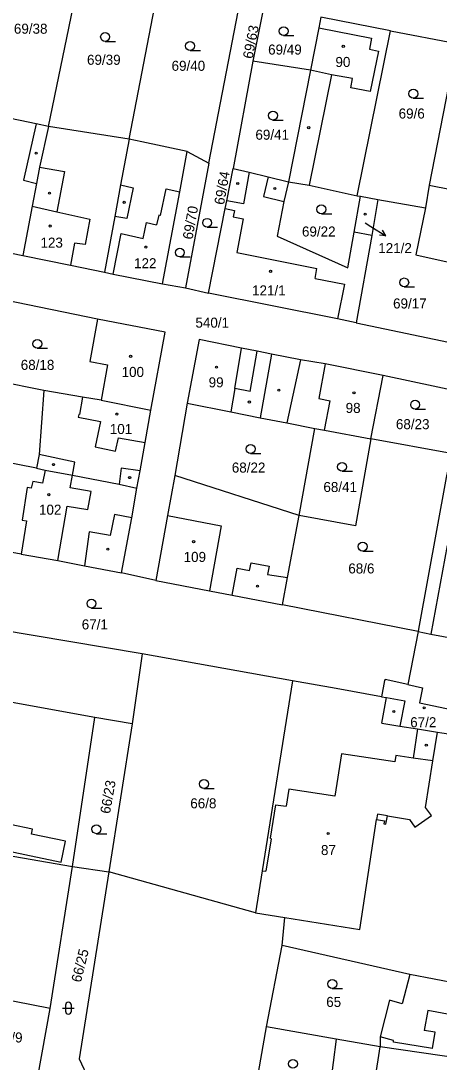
# Model space of a CAD drawing. Extents: x -758582 to -751794, y -998770 to -994350.
# Drawn here: x -756568.2 to -756497.4, y -996870.6 to -996694.2 of the extents above; entities that cross this region are included whole.
import ezdxf

# ---------------------------------------------------------------- set-up
doc = ezdxf.new("R2010")
doc.units = 0
for name, color, linetype in [('Hranice parcel', 7, 'Continuous'), ('Parcelní čísla', 7, 'Continuous'), ('Pop  PČ popisy', 7, 'Continuous'), ('Vnitřní kresba', 7, 'Continuous'), ('Značky budov', 7, 'Continuous'), ('Značky kultur', 7, 'Continuous')]:
    doc.layers.add(name, color=color, linetype=linetype)

msp = doc.modelspace()

# ---------------------------------------------------------------- linework, layer by layer
at = {"layer": 'Hranice parcel'}
for p, q in [((-756563.55, -996712.15), (-756558.07, -996685.62)), ((-756549.87, -996714.27), (-756544.86, -996688.3)), ((-756536.42, -996718.33), (-756531.1, -996690.92)), ((-756527.09, -996691.75), (-756528.96, -996701.04)), ((-756505.62, -996695.91), (-756517.41, -996693.6)), ((-756511.28, -996723.85), (-756505.62, -996695.91)), ((-756505.62, -996695.91), (-756494.42, -996698.08)), ((-756528.96, -996701.04), (-756532.3, -996719.25)), ((-756519.19, -996702.61), (-756528.96, -996701.04)), ((-756519.19, -996702.61), (-756522.92, -996721.49)), ((-756549.87, -996714.27), (-756563.55, -996712.15)), ((-756540.07, -996716.36), (-756536.42, -996718.33)), ((-756536.42, -996718.33), (-756540.33, -996739.42)), ((-756511.79, -996730), (-756510.7, -996723.94)), ((-756511.28, -996723.85), (-756510.7, -996723.94)), ((-756510.7, -996723.94), (-756507.76, -996724.5)), ((-756507.76, -996724.5), (-756508.8, -996730.61)), ((-756507.76, -996724.5), (-756499.71, -996725.9)), ((-756508.8, -996730.61), (-756511.79, -996730)), ((-756508.8, -996730.61), (-756511.47, -996745.39)), ((-756544.26, -996738.78), (-756540.33, -996739.42)), ((-756540.33, -996739.42), (-756536.47, -996740.33)), ((-756555.24, -996744.76), (-756570.89, -996741.53)), ((-756511.47, -996745.39), (-756491.64, -996749.52)), ((-756525.81, -996750.65), (-756527.73, -996761.44)), ((-756564.37, -996756.81), (-756573.85, -996754.94)), ((-756508.94, -996765), (-756506.9, -996754.31)), ((-756492.81, -996757.29), (-756506.9, -996754.31)), ((-756554.62, -996758.49), (-756546.23, -996760.16)), ((-756540.05, -996758.95), (-756542.15, -996771.23)), ((-756521.08, -996777.98), (-756518.43, -996763.24)), ((-756495.38, -996767.47), (-756508.94, -996765)), ((-756565.56, -996769.98), (-756576.24, -996767.9)), ((-756565.56, -996769.98), (-756564.11, -996770.31)), ((-756521.08, -996777.98), (-756542.15, -996771.23)), ((-756568.17, -996784.53), (-756578.57, -996782.73)), ((-756545.35, -996788.99), (-756551.2, -996787.73)), ((-756547.67, -996801.44), (-756605.96, -996791.65)), ((-756500.94, -996797.64), (-756523.93, -996793.11)), ((-756500.94, -996797.64), (-756502.69, -996806.62)), ((-756555.71, -996812.22), (-756608.12, -996802.73)), ((-756547.67, -996801.44), (-756549.41, -996813.29)), ((-756522.21, -996805.99), (-756547.67, -996801.44)), ((-756559.51, -996837.41), (-756555.71, -996812.22)), ((-756549.41, -996813.29), (-756555.71, -996812.22)), ((-756549.41, -996813.29), (-756553.36, -996838.32)), ((-756589.42, -996832.3), (-756559.51, -996837.41)), ((-756563.27, -996861.47), (-756559.51, -996837.41)), ((-756559.51, -996837.41), (-756553.36, -996838.32)), ((-756526.61, -996864.58), (-756524.01, -996850.79)), ((-756502.39, -996855.73), (-756524.01, -996850.79)), ((-756563.27, -996861.47), (-756578.06, -996858.62)), ((-756565.33, -996873.04), (-756563.27, -996861.47)), ((-756529.05, -996878.16), (-756526.61, -996864.58)), ((-756514.82, -996866.64), (-756526.61, -996864.58)), ((-756514.82, -996866.64), (-756516.57, -996880.2)), ((-756507.38, -996867.95), (-756514.82, -996866.64)), ((-756486.94, -996870.94), (-756507.38, -996867.95))]:
    msp.add_line(p, q, dxfattribs=at)
for points in [[(-756517.41, -996693.6), (-756517.79, -996695.43), (-756519.19, -996702.61)], [(-756494.42, -996698.08), (-756499.07, -996722.09), (-756499.71, -996725.9)], [(-756563.55, -996712.15), (-756565.64, -996711.66), (-756578.46, -996709.01)], [(-756563.55, -996712.15), (-756565.09, -996719.02), (-756565.59, -996721.76), (-756566.31, -996725.61), (-756567.88, -996733.95)], [(-756549.87, -996714.27), (-756551.36, -996722.02), (-756552.3, -996727.37), (-756554.06, -996736.78)], [(-756540.07, -996716.36), (-756547.74, -996714.72), (-756549.87, -996714.27)], [(-756544.26, -996738.78), (-756541.31, -996723.17), (-756540.07, -996716.36)], [(-756536.47, -996740.33), (-756533.64, -996726.04), (-756533.37, -996724.73), (-756532.3, -996719.25)], [(-756532.3, -996719.25), (-756529.56, -996719.87), (-756526.33, -996720.64), (-756522.92, -996721.49)], [(-756522.92, -996721.49), (-756523.69, -996724.84), (-756524.85, -996730.71), (-756512.87, -996736.05), (-756511.79, -996730)], [(-756522.92, -996721.49), (-756519.39, -996722.05), (-756511.28, -996723.85)], [(-756499.71, -996725.9), (-756501.33, -996733.87), (-756489.44, -996736.5)], [(-756582.73, -996730.98), (-756572.06, -996733.11), (-756567.88, -996733.95)], [(-756567.88, -996733.95), (-756559.84, -996735.6), (-756554.06, -996736.78)], [(-756554.06, -996736.78), (-756552.58, -996737.11), (-756544.26, -996738.78)], [(-756511.47, -996745.39), (-756514.61, -996744.7), (-756536.47, -996740.33)], [(-756555.24, -996744.76), (-756556.57, -996751.91), (-756553.54, -996752.46), (-756554.62, -996758.49)], [(-756546.23, -996760.16), (-756543.78, -996746.97), (-756555.24, -996744.76)], [(-756525.81, -996750.65), (-756528.19, -996750.19), (-756530.87, -996749.64), (-756538.05, -996748.18), (-756540.05, -996758.95)], [(-756506.9, -996754.31), (-756516.72, -996752.34), (-756520.86, -996751.62), (-756525.81, -996750.65)], [(-756564.37, -996756.81), (-756565.14, -996767.64), (-756565.56, -996769.98)], [(-756554.62, -996758.49), (-756557.81, -996757.98), (-756564.37, -996756.81)], [(-756548.59, -996773.36), (-756548.01, -996770.43), (-756547.2, -996765.62), (-756546.23, -996760.16)], [(-756540.05, -996758.95), (-756532.68, -996760.44), (-756527.73, -996761.44)], [(-756527.73, -996761.44), (-756523.18, -996762.32), (-756518.43, -996763.24)], [(-756518.43, -996763.24), (-756516.81, -996763.54), (-756508.94, -996765)], [(-756508.94, -996765), (-756511.54, -996779.77), (-756521.08, -996777.98)], [(-756495.38, -996767.47), (-756496.21, -996771.56), (-756500.87, -996797.26), (-756500.94, -996797.64)], [(-756564.11, -996770.31), (-756564.57, -996772.53), (-756566.19, -996772.22), (-756566.47, -996773.35), (-756567.16, -996773.25), (-756568.01, -996778.77), (-756567.3, -996778.88), (-756568.17, -996784.53)], [(-756564.11, -996770.31), (-756559.5, -996771.19), (-756551.56, -996772.71), (-756548.59, -996773.36)], [(-756542.15, -996771.23), (-756543.4, -996777.98), (-756545.35, -996788.99)], [(-756551.2, -996787.73), (-756549.42, -996778.38), (-756548.59, -996773.36)], [(-756523.93, -996793.11), (-756523.09, -996788.49), (-756521.08, -996777.98)], [(-756568.17, -996784.53), (-756561.98, -996785.61), (-756557.48, -996786.54), (-756551.2, -996787.73)], [(-756545.35, -996788.99), (-756536.29, -996790.75), (-756532.44, -996791.51), (-756523.93, -996793.11)], [(-756500.94, -996797.64), (-756498.78, -996798.07), (-756477.04, -996802.1), (-756475.28, -996802.36)], [(-756522.21, -996805.99), (-756527.35, -996838.15), (-756528.5, -996845.28), (-756553.36, -996838.32)], [(-756507.14, -996808.69), (-756514.86, -996807.31), (-756522.21, -996805.99)], [(-756502.69, -996806.62), (-756506.56, -996805.74), (-756506.63, -996805.93), (-756507.14, -996808.69)], [(-756502.69, -996806.62), (-756500.21, -996807.19), (-756500.75, -996809.74), (-756496.18, -996810.67), (-756478.74, -996813.46), (-756477.06, -996813.73)], [(-756507.14, -996808.69), (-756506.32, -996808.84), (-756503.23, -996809.39), (-756504.06, -996813.66), (-756501.09, -996814.13), (-756497.68, -996814.67)], [(-756524.01, -996850.79), (-756523.54, -996846.08), (-756510.83, -996848.12), (-756508.01, -996829.46), (-756506.63, -996829.7), (-756506.74, -996830.19), (-756506.44, -996830.25), (-756506.17, -996828.87), (-756502.44, -996829.47), (-756501.5, -996830.77), (-756498.72, -996828.79), (-756499.7, -996827.45), (-756498.45, -996819.55), (-756497.68, -996814.67)], [(-756497.68, -996814.67), (-756496.92, -996814.78), (-756479.42, -996817.44), (-756477.69, -996817.74)], [(-756574.07, -996830.32), (-756579.21, -996829.3), (-756579.91, -996832.82), (-756561.43, -996836.71), (-756560.65, -996833.16), (-756566.43, -996831.95), (-756566.26, -996831.09), (-756573.9, -996829.5), (-756574.07, -996830.32)], [(-756553.36, -996838.32), (-756558.36, -996870.02), (-756556.72, -996873.48)], [(-756502.39, -996855.73), (-756503.67, -996860.68), (-756505.81, -996860.06), (-756507.38, -996866.25), (-756507.38, -996867.95)], [(-756485.2, -996859), (-756485.89, -996858.89), (-756502.39, -996855.73)]]:
    msp.add_lwpolyline(points, dxfattribs=at)
at = {"layer": 'Pop  PČ popisy'}
for p, q in [((-756509.93, -996728.42), (-756508.95, -996729.04)), ((-756508.95, -996729.04), (-756506.41, -996730.63)), ((-756506.41, -996730.63), (-756507.52, -996730.52)), ((-756506.41, -996730.63), (-756506.99, -996729.68))]:
    msp.add_line(p, q, dxfattribs=at)
at = {"layer": 'Vnitřní kresba'}
for p, q in [((-756517.79, -996695.43), (-756508.83, -996697.15)), ((-756508.83, -996697.15), (-756509.2, -996699.03)), ((-756509.2, -996699.03), (-756507.68, -996699.4)), ((-756507.68, -996699.4), (-756509.1, -996706.19)), ((-756515.62, -996703.36), (-756519.39, -996722.05)), ((-756515.62, -996703.36), (-756519.19, -996702.61)), ((-756512.06, -996703.98), (-756515.62, -996703.36)), ((-756512.36, -996705.58), (-756512.06, -996703.98)), ((-756509.1, -996706.19), (-756512.36, -996705.58)), ((-756565.64, -996711.66), (-756567.78, -996721.24)), ((-756565.09, -996719.02), (-756560.85, -996719.73)), ((-756560.85, -996719.73), (-756562.16, -996726.55)), ((-756529.56, -996719.87), (-756530.55, -996725.22)), ((-756567.78, -996721.24), (-756565.59, -996721.76)), ((-756526.33, -996720.64), (-756527.14, -996724)), ((-756551.36, -996722.02), (-756549.22, -996722.49)), ((-756549.22, -996722.49), (-756550.27, -996727.71)), ((-756544.56, -996727.19), (-756543.65, -996722.71)), ((-756543.65, -996722.71), (-756541.31, -996723.17)), ((-756499.07, -996722.09), (-756495.37, -996722.8)), ((-756530.55, -996725.22), (-756533.37, -996724.73)), ((-756527.14, -996724), (-756523.69, -996724.84)), ((-756566.31, -996725.61), (-756562.16, -996726.55)), ((-756562.16, -996726.55), (-756556.54, -996727.82)), ((-756533.64, -996726.04), (-756532.03, -996726.33)), ((-756532.03, -996726.33), (-756532.27, -996727.42)), ((-756556.54, -996727.82), (-756557.32, -996732.13)), ((-756550.27, -996727.71), (-756552.3, -996727.37)), ((-756547.54, -996731.07), (-756546.98, -996728.4)), ((-756546.98, -996728.4), (-756545.24, -996728.76)), ((-756544.87, -996727.12), (-756545.24, -996728.76)), ((-756544.56, -996727.19), (-756544.87, -996727.12)), ((-756532.27, -996727.42), (-756530.6, -996727.77)), ((-756530.6, -996727.77), (-756531.66, -996733.46)), ((-756552.58, -996737.11), (-756551.25, -996730.22)), ((-756551.25, -996730.22), (-756547.54, -996731.07)), ((-756559.13, -996731.9), (-756559.84, -996735.6)), ((-756557.32, -996732.13), (-756559.13, -996731.9)), ((-756531.66, -996733.46), (-756518.1, -996736.16)), ((-756518.38, -996737.89), (-756518.1, -996736.16)), ((-756518.38, -996737.89), (-756513.43, -996738.85)), ((-756513.43, -996738.85), (-756514.61, -996744.7)), ((-756532.02, -996756.49), (-756530.87, -996749.64)), ((-756529.4, -996757.02), (-756528.19, -996750.19)), ((-756520.86, -996751.62), (-756523.18, -996762.32)), ((-756516.72, -996752.34), (-756517.75, -996758.16)), ((-756532.02, -996756.49), (-756532.68, -996760.44)), ((-756529.4, -996757.02), (-756532.02, -996756.49)), ((-756557.81, -996757.98), (-756558.28, -996760.91)), ((-756517.75, -996758.16), (-756515.85, -996758.56)), ((-756516.81, -996763.54), (-756515.85, -996758.56)), ((-756558.43, -996760.89), (-756558.52, -996761.37)), ((-756558.52, -996761.37), (-756554.74, -996762.08)), ((-756558.28, -996760.91), (-756558.43, -996760.89)), ((-756554.74, -996762.08), (-756555.64, -996766.36)), ((-756552.21, -996767.11), (-756551.7, -996764.85)), ((-756551.7, -996764.85), (-756547.2, -996765.62)), ((-756555.64, -996766.36), (-756552.21, -996767.11)), ((-756559.08, -996768.99), (-756565.14, -996767.64)), ((-756559.5, -996771.19), (-756559.08, -996768.99)), ((-756551.24, -996770), (-756551.56, -996772.71)), ((-756548.01, -996770.43), (-756551.24, -996770)), ((-756559.87, -996773.31), (-756559.5, -996771.19)), ((-756556.34, -996773.96), (-756559.87, -996773.31)), ((-756556.89, -996776.99), (-756556.34, -996773.96)), ((-756561.98, -996785.61), (-756560.41, -996776.43)), ((-756560.41, -996776.43), (-756556.89, -996776.99)), ((-756552.36, -996777.85), (-756553.09, -996781.39)), ((-756549.42, -996778.38), (-756552.36, -996777.85)), ((-756543.4, -996777.98), (-756534.29, -996779.72)), ((-756534.29, -996779.72), (-756536.29, -996790.75)), ((-756556.64, -996780.75), (-756557.48, -996786.54)), ((-756553.09, -996781.39), (-756556.64, -996780.75)), ((-756496.04, -996783.1), (-756498.78, -996798.07)), ((-756532.44, -996791.51), (-756531.59, -996786.92)), ((-756531.59, -996786.92), (-756529.51, -996787.29)), ((-756529.51, -996787.29), (-756529.26, -996785.99)), ((-756529.26, -996785.99), (-756526.18, -996786.6)), ((-756526.18, -996786.6), (-756526.45, -996787.99)), ((-756526.45, -996787.99), (-756523.09, -996788.49)), ((-756507.09, -996813.15), (-756506.32, -996808.84)), ((-756507.09, -996813.15), (-756504.06, -996813.66)), ((-756501.09, -996814.13), (-756501.79, -996819.06)), ((-756513.96, -996818.33), (-756515.08, -996825.53)), ((-756504.93, -996819.68), (-756513.96, -996818.33)), ((-756504.76, -996818.62), (-756504.93, -996819.68)), ((-756501.79, -996819.06), (-756504.76, -996818.62)), ((-756498.45, -996819.55), (-756501.79, -996819.06)), ((-756522.84, -996824.34), (-756523.31, -996827.23)), ((-756515.08, -996825.53), (-756522.84, -996824.34)), ((-756525.09, -996826.96), (-756526.01, -996832.65)), ((-756525.09, -996826.96), (-756523.31, -996827.23)), ((-756507.84, -996828.58), (-756508.01, -996829.46)), ((-756506.17, -996828.87), (-756507.84, -996828.58)), ((-756525.84, -996832.72), (-756526.75, -996838.23)), ((-756525.84, -996832.72), (-756526.01, -996832.65)), ((-756527.35, -996838.15), (-756526.75, -996838.23)), ((-756528.5, -996845.28), (-756523.54, -996846.08)), ((-756499.29, -996861.82), (-756499.93, -996865.19)), ((-756495.38, -996862.55), (-756499.29, -996861.82)), ((-756505.11, -996866.88), (-756507.38, -996866.25)), ((-756498.1, -996865.46), (-756499.93, -996865.19)), ((-756498.55, -996868.27), (-756498.1, -996865.46)), ((-756508.25, -996873.44), (-756507.38, -996867.95)), ((-756505.14, -996867.2), (-756505.11, -996866.88)), ((-756498.55, -996868.27), (-756505.14, -996867.2))]:
    msp.add_line(p, q, dxfattribs=at)
at = {"layer": 'Značky budov'}
for centre in [(-756513.63, -996698.55), (-756519.49, -996712.33), (-756565.63, -996716.64), (-756531.51, -996721.79), (-756563.37, -996723.43), (-756525.24, -996722.61), (-756550.73, -996724.97), (-756509.94, -996726.96), (-756563.27, -996728.98), (-756547.06, -996732.54), (-756525.94, -996736.65), (-756549.64, -996751.05), (-756535.09, -996752.87), (-756524.54, -996756.79), (-756529.54, -996758.78), (-756511.82, -996757.21), (-756551.97, -996760.82), (-756562.69, -996769.38), (-756549.81, -996771.58), (-756563.51, -996774.47), (-756538.97, -996782.43), (-756553.51, -996783.71), (-756528.15, -996789.97), (-756505.07, -996811.2), (-756499.93, -996810.56), (-756499.57, -996816.88), (-756516.19, -996831.83)]:
    msp.add_circle(centre, 0.175, dxfattribs=at)
at = {"layer": 'Značky kultur'}
for p, q in [((-756523.73, -996696.74), (-756521.98, -996696.74)), ((-756553.97, -996697.71), (-756552.22, -996697.71)), ((-756539.58, -996699.24), (-756537.83, -996699.24)), ((-756501.78, -996707.32), (-756500.03, -996707.32)), ((-756525.54, -996711.03), (-756523.79, -996711.03)), ((-756517.35, -996726.91), (-756515.6, -996726.91)), ((-756536.69, -996729.18), (-756534.94, -996729.18)), ((-756541.31, -996734.22), (-756539.56, -996734.22)), ((-756503.31, -996739.28), (-756501.56, -996739.28)), ((-756565.45, -996749.68), (-756563.7, -996749.68)), ((-756501.47, -996759.98), (-756499.72, -996759.98)), ((-756529.33, -996767.48), (-756527.58, -996767.48)), ((-756513.84, -996770.5), (-756512.09, -996770.5)), ((-756510.35, -996784.01), (-756508.6, -996784.01)), ((-756556.28, -996793.66), (-756554.53, -996793.66)), ((-756537.22, -996824.21), (-756535.47, -996824.21)), ((-756555.44, -996831.87), (-756553.69, -996831.87)), ((-756515.5, -996858.07), (-756513.75, -996858.07)), ((-756560.68, -996860.92), (-756560.68, -996861.92)), ((-756559.68, -996861.92), (-756559.68, -996860.92)), ((-756561.18, -996861.42), (-756559.18, -996861.42))]:
    msp.add_line(p, q, dxfattribs=at)
for centre in [(-756523.73, -996695.99), (-756553.97, -996696.96), (-756539.58, -996698.49), (-756501.78, -996706.57), (-756525.54, -996710.28), (-756517.35, -996726.16), (-756536.69, -996728.43), (-756541.31, -996733.47), (-756503.31, -996738.53), (-756565.45, -996748.93), (-756501.47, -996759.23), (-756529.33, -996766.73), (-756513.84, -996769.75), (-756510.35, -996783.26), (-756556.28, -996792.91), (-756537.22, -996823.46), (-756555.44, -996831.12), (-756515.5, -996857.32), (-756522.16, -996870.84)]:
    msp.add_circle(centre, 0.75, dxfattribs=at)
for centre, start, end in [((-756560.18, -996860.92), 0, 180), ((-756560.18, -996861.92), 180, 359.9879)]:
    msp.add_arc(centre, 0.5, start, end, dxfattribs=at)

# ---------------------------------------------------------------- texts
at = {"layer": 'Parcelní čísla'}
for s, p in [('69/38', (-756569.41, -996696.42)), ('69/49', (-756526.36, -996699.95)), ('69/39', (-756557.03, -996701.68)), ('90', (-756514.96, -996702.05)), ('69/40', (-756542.71, -996702.7)), ('69/6', (-756504.26, -996710.78)), ('69/41', (-756528.51, -996714.37)), ('69/22', (-756520.63, -996730.76)), ('123', (-756564.91, -996732.64)), ('121/2', (-756507.71, -996733.57)), ('122', (-756549.06, -996736.13)), ('121/1', (-756529.08, -996740.73)), ('69/17', (-756505.2, -996742.94)), ('540/1', (-756538.67, -996746.19)), ('68/18', (-756568.25, -996753.34)), ('100', (-756551.17, -996754.54)), ('99', (-756536.43, -996756.3)), ('98', (-756513.23, -996760.63)), ('68/23', (-756504.72, -996763.38)), ('101', (-756553.17, -996764.2)), ('68/22', (-756532.51, -996770.73)), ('68/41', (-756517, -996774.02)), ('102', (-756565.16, -996777.86)), ('109', (-756540.67, -996785.86)), ('68/6', (-756512.78, -996787.81)), ('67/1', (-756557.92, -996797.29)), ('67/2', (-756502.3, -996813.85)), ('66/8', (-756539.54, -996827.58)), ('87', (-756517.41, -996835.49)), ('65', (-756516.52, -996861.21)), ('66/9', (-756572.37, -996867.23))]:
    msp.add_text(s, height=1.7, dxfattribs=at).set_placement(p)
for s, rotation, p in [('69/63', 79, (-756529, -996700.76)), ('69/64', 80, (-756533.83, -996725.48)), ('69/70', 80, (-756539.18, -996731.35)), ('66/23', 80, (-756553.15, -996828.59)), ('66/25', 76, (-756558.08, -996857.16))]:
    msp.add_text(s, height=1.7, rotation=rotation, dxfattribs=at).set_placement(p)

doc.saveas('drawing.dxf')
